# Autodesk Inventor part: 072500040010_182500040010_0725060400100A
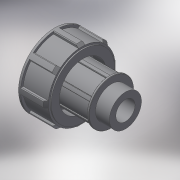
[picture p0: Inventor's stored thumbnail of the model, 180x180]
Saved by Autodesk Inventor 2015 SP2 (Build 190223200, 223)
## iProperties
Created: 2017-04
Part Number: 072500040010_182500040010_0725060400100A
Material: Generic
Description: PLASSON THREADED ADAPTOR 40-1"
Document SubType Name: Modeling
Designer: KIM
Density: 1 g/cm^3
Appearance: Default
Author: KIM
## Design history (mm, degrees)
derived "07250.ipt"
feature "Solid1::07250.ipt"
tag "TaggingFeature1"
body "Solid1"
other parameters: "d1" = 33.249, "d2" = 99, "d6" = 82, "d7" = 76.26, "d8" = 65.6, "d10" = 46.5486, "d12" = 19.9494, "d13" = 26.5992, "d14" = 23, "d15" = 61.5, "d16" = 2.97, "d17" = 39.6, "d19" = 24, "d24" = 6.6498, "d25" = 3.3249, "d27" = 0, "d28" = 2.65992, "d31" = 0.66498, "d35" = 360 deg, "d41" = 29.337, "d56" = 44, "d57" = 4, "d58" = 2, "d60" = 0, "d61" = 0.33249, "d64" = 0.33249, "d68" = 360 deg, "R_" = 33.249, "E_" = 82, "H_" = 99
